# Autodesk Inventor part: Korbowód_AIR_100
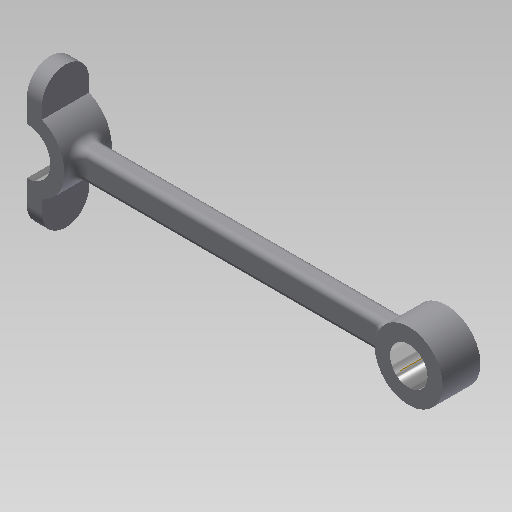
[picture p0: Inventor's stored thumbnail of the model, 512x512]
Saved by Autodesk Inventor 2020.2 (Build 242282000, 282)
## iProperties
Created: 2014-10
Part Number: Korbowód_AIR_100
Material: Ogólny
Document SubType Name: Modeling
Designer: F.Stasiak
Density: 1 g/cm^3
Appearance: Domyślna
Catalog Web Link: www.expertbooks.pl
Manager: www.cadconsulting.pl
Company: Fabian Stasiak CAD Consulting
Author: F.Stasiak
Subject: Zbiór ćwiczeń. Autodesk Inventor 2020. Kurs Professional
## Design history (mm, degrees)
sketch "Szkic1"
  geometry: L1 (0, -20)-(0, 20); A1 r 12.5 centre (0, 0) between (0, -12.5) and (0, 12.5); A2 r 20 centre (0, 0) between (0, -20) and (0, 20); 2 further points
  constraints: 4 point on circle, 3 coincident, 2 centre point, 2 end point, 2 point on line, 1 midpoint, 1 vertical
  dimensions: "d0" = 25 diameter of A1; "d1" = 40 diameter of A2
extrude "Wyciągnięcie proste1" new body sketch "Szkic1" stored distance "d2" = 25; taper "d3" = 0 deg
sketch "Szkic2"
  geometry: L1 (183.637, -7.5)-(18.54, -7.5); L2 (183.637, 7.5)-(18.54, 7.5); L3 (200, 0)-(0, 0); C1 r 10 at (200, 0); A1 r 20 centre (0, 0) between (0, -20) and (0, 20) reference; A2 r 18 centre (200, 0) between (183.637, -7.5) and (183.637, 7.5); 1 further point
  constraints: 6 end point, 4 point on circle, 2 centre point, 2 horizontal, 1 parallel, 1 other
  dimensions: "d4" = 20 diameter of C1; "d5" = 200 distance of point (0, 0) L3.start; "d6" = 8 radial gap between concentric circles of C1 A2; "d7" = 15 distance between parallel lines of L2 L1
extrude "Wyciągnięcie proste2" join sketch "Szkic2" stored distance "d8" = 10; taper "d9" = 0 deg
extrude "Wyciągnięcie proste3" join sketch "Szkic2" stored distance "d10" = 20; taper "d11" = 0 deg
fillet "Zaokrąglenie1" dims "d12" = 3
fillet "Zaokrąglenie2" dims "d13" = 5
sketch "Szkic3"
  geometry: L1 (0, 0)-(-25, 0) reference; L2 (0, 7.5)-(0, 0) reference; L3 (-25, 7.5)-(0, 7.5) reference; L4 (-25, 0)-(-25, 7.5) reference; L5 (-25, 32.5)-(0, 32.5) reference; L6 (0, 40)-(0, 32.5) reference; L7 (-25, 40)-(0, 40) reference; L8 (-25, 32.5)-(-25, 40) reference; L9 (-25, 0)-(-25, -5); L10 (0, -5)-(0, 0); A1 r 12.5 centre (-12.5, -5) between (-25, -5) and (0, -5); 1 further point
  constraints: 4 end point, 2 point on circle, 2 tangent, 1 centre point, 1 parallel, 1 vertical
  dimensions: "d14" = 25 vertical distance of point (-12.5, 20) L10.start
extrude "Wyciągnięcie proste4" join sketch "Szkic3" distance "d15" = 8; taper "d16" = 0 deg
mirror "Odbicie lustrzane1"
node "Punkt konstrukcyjny1"
  node "Oś konstrukcyjna1"
node "Bryła1"
node "Pętla rzutowana1"
node "Pętla rzutowana2"
